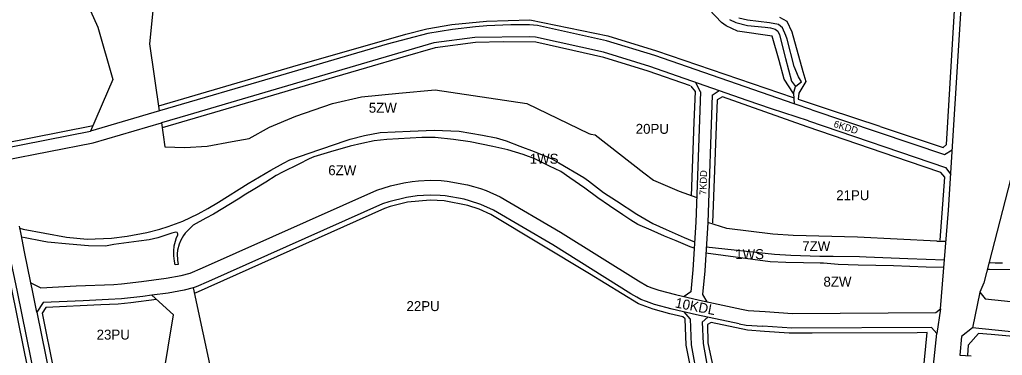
# Model space of a CAD drawing. Extents: x 7428203 to 7432868, y 5542672 to 5545406.
# Drawn here: x 7430430 to 7431420, y 5544524 to 5544863 of the extents above; entities that cross this region are included whole.
import ezdxf

# ---------------------------------------------------------------- set-up
doc = ezdxf.new("R2010")
doc.units = 0
for name, color, linetype in [('_GRANICA_MIASTA', 7, 'Continuous'), ('granicaBulwary', 7, 'Continuous'), ('MPZP_uchwalone_nieobowiazujace jeszcze_SZRAF', 7, 'Continuous')]:
    doc.layers.add(name, color=color, linetype=linetype)

msp = doc.modelspace()

# ---------------------------------------------------------------- linework, layer by layer
at = {"layer": '_GRANICA_MIASTA'}
for p, q in [((7430403.81, 5545093.47), (7430508.77, 5544854.93)), ((7431365.56, 5544670.63), (7431383.69, 5544964.48)), ((7430561.2, 5544838.24), (7430570.79, 5544936.38)), ((7431145.02, 5544862.64), (7431151.24, 5544859.72)), ((7431151.24, 5544859.72), (7431163.08, 5544856.79)), ((7430508.77, 5544854.93), (7430523.8, 5544802.28)), ((7430841.3, 5544848.45), (7430800.25, 5544837.84)), ((7430865.99, 5544852.6), (7430841.3, 5544848.45)), ((7430889.02, 5544855.39), (7430865.99, 5544852.6)), ((7430900.65, 5544856.15), (7430889.02, 5544855.39)), ((7430924.73, 5544857.4), (7430900.65, 5544856.15)), ((7430943.5, 5544857.43), (7430924.73, 5544857.4)), ((7430951.44, 5544856.57), (7430943.5, 5544857.43)), ((7431021.13, 5544841.34), (7430951.44, 5544856.57)), ((7431163.08, 5544856.79), (7431181.02, 5544854.93)), ((7431181.02, 5544854.93), (7431186.08, 5544854.4)), ((7431186.08, 5544854.4), (7431191.09, 5544853.08)), ((7431191.09, 5544853.08), (7431193.77, 5544851.02)), ((7431193.77, 5544851.02), (7431195.22, 5544847.14)), ((7430847.35, 5544839.01), (7430743.03, 5544808.53)), ((7430888.49, 5544844.44), (7430847.35, 5544839.01)), ((7430943.35, 5544845.35), (7430888.49, 5544844.44)), ((7430949.65, 5544844.83), (7430943.35, 5544845.35)), ((7431018.07, 5544829.73), (7430949.65, 5544844.83)), ((7431069.71, 5544826.5), (7431021.13, 5544841.34)), ((7431195.22, 5544847.14), (7431201.29, 5544823.27)), ((7430571.05, 5544770.59), (7430561.2, 5544838.24)), ((7430800.25, 5544837.84), (7430692.89, 5544806.33)), ((7431064.73, 5544815.47), (7431018.07, 5544829.73)), ((7431210.02, 5544777.67), (7431069.71, 5544826.5)), ((7431201.29, 5544823.27), (7431207.5, 5544800.46)), ((7431162.79, 5544781.23), (7431064.73, 5544815.47)), ((7430523.8, 5544802.28), (7430501.57, 5544750.21)), ((7430692.89, 5544806.33), (7430571.05, 5544770.59)), ((7430743.03, 5544808.53), (7430599.4, 5544766.41)), ((7431115.79, 5544789.85), (7431110.76, 5544799.4)), ((7431207.5, 5544800.46), (7431211.4, 5544795.35)), ((7430811.81, 5544788.58), (7430848.68, 5544791.74)), ((7430848.68, 5544791.74), (7430940.83, 5544778.13)), ((7431115.79, 5544789.85), (7431111, 5544658.59)), ((7431127.61, 5544786.5), (7431134.58, 5544791.08)), ((7430745.25, 5544778.21), (7430774.51, 5544784.82)), ((7430774.51, 5544784.82), (7430811.81, 5544788.58)), ((7431127.61, 5544786.5), (7431122.99, 5544658.15)), ((7431187.25, 5544772.69), (7431162.79, 5544781.23)), ((7431209.44, 5544788.08), (7431210.02, 5544777.67)), ((7430571.05, 5544770.59), (7430501.57, 5544750.21)), ((7430708.23, 5544765.47), (7430745.25, 5544778.21)), ((7430940.83, 5544778.13), (7431003.36, 5544748)), ((7431224.37, 5544760.47), (7431187.25, 5544772.69)), ((7431227.72, 5544771.68), (7431210.02, 5544777.67)), ((7431227.72, 5544771.68), (7431361.56, 5544726.7)), ((7430599.4, 5544766.41), (7430572.79, 5544758.6)), ((7430681.56, 5544754.21), (7430708.23, 5544765.47)), ((7430504.28, 5544738.51), (7430572.79, 5544758.6)), ((7430572.79, 5544758.6), (7430576.3, 5544734.53)), ((7430661.36, 5544742.68), (7430681.56, 5544754.21)), ((7430619.03, 5544735.1), (7430644.11, 5544739.65)), ((7430644.11, 5544739.65), (7430661.36, 5544742.68)), ((7431003.36, 5544748), (7431005.28, 5544747.05)), ((7431005.28, 5544747.05), (7431009.5, 5544746.41)), ((7431009.5, 5544746.41), (7431058.51, 5544708.25)), ((7430576.3, 5544734.53), (7430596.47, 5544733.89)), ((7430596.47, 5544733.89), (7430619.03, 5544735.1)), ((7431361.56, 5544726.7), (7431369.31, 5544731.46)), ((7430825.25, 5544699.49), (7430831.85, 5544700.17)), ((7430831.85, 5544700.17), (7430843.59, 5544700.67)), ((7430843.59, 5544700.67), (7430854.46, 5544700.34)), ((7430854.46, 5544700.34), (7430860.64, 5544699.81)), ((7431058.51, 5544708.25), (7431068.41, 5544701)), ((7431068.41, 5544701), (7431094.28, 5544689.83)), ((7430614.27, 5544612.53), (7430789.81, 5544690.81)), ((7430789.81, 5544690.81), (7430803.47, 5544695.18)), ((7430803.47, 5544695.18), (7430816.98, 5544698.24)), ((7430816.98, 5544698.24), (7430825.25, 5544699.49)), ((7430860.64, 5544699.81), (7430880.99, 5544696.26)), ((7430880.99, 5544696.26), (7430887.3, 5544694.58)), ((7430887.3, 5544694.58), (7430894.33, 5544692.36)), ((7430894.33, 5544692.36), (7430899.97, 5544690.31)), ((7430899.97, 5544690.31), (7430914.06, 5544684.05)), ((7430819.63, 5544683.47), (7430801.98, 5544679.1)), ((7430830.27, 5544684.96), (7430819.63, 5544683.47)), ((7430836.63, 5544685.46), (7430830.27, 5544684.96)), ((7430843.61, 5544685.67), (7430836.63, 5544685.46)), ((7430853.49, 5544685.37), (7430843.61, 5544685.67)), ((7430858.6, 5544684.94), (7430853.49, 5544685.37)), ((7430877.77, 5544681.6), (7430858.6, 5544684.94)), ((7430883.11, 5544680.17), (7430877.77, 5544681.6)), ((7430894.36, 5544676.39), (7430883.11, 5544680.17)), ((7430914.06, 5544684.05), (7430974.84, 5544648.56)), ((7431094.28, 5544689.83), (7431111.9, 5544683.37)), ((7430795.4, 5544676.88), (7430620.35, 5544598.82)), ((7430801.98, 5544679.1), (7430795.4, 5544676.88)), ((7430907.22, 5544670.68), (7430894.36, 5544676.39)), ((7430967.07, 5544635.73), (7430907.22, 5544670.68)), ((7431357.47, 5544571.25), (7431365.56, 5544670.63)), ((7430431.55, 5544646.37), (7430429.88, 5544654.63)), ((7430435.12, 5544628.69), (7430431.55, 5544646.37)), ((7430974.84, 5544648.56), (7431053.21, 5544599.28)), ((7431209.07, 5544645.23), (7431188.63, 5544646.48)), ((7431273.81, 5544643.32), (7431209.07, 5544645.23)), ((7431353.8, 5544639.43), (7431273.81, 5544643.32)), ((7431045.61, 5544586.34), (7430967.07, 5544635.73)), ((7431353.8, 5544639.43), (7431363.01, 5544639.34)), ((7430441.47, 5544597.29), (7430435.12, 5544628.69)), ((7430601.92, 5544607.08), (7430614.27, 5544612.53)), ((7430552.94, 5544598.65), (7430577.56, 5544601.96)), ((7430577.56, 5544601.96), (7430592.8, 5544604.73)), ((7430592.8, 5544604.73), (7430601.92, 5544607.08)), ((7430441.47, 5544597.29), (7430451.33, 5544592.35)), ((7430442.65, 5544591.45), (7430441.47, 5544597.29)), ((7430447.41, 5544567.9), (7430442.65, 5544591.45)), ((7430451.33, 5544592.35), (7430487, 5544594.33)), ((7430487, 5544594.33), (7430525.05, 5544595.88)), ((7430525.05, 5544595.88), (7430532.62, 5544596.25)), ((7430532.62, 5544596.25), (7430552.94, 5544598.65)), ((7430604.98, 5544592.38), (7430595.88, 5544590.06)), ((7430607.98, 5544593.36), (7430604.98, 5544592.38)), ((7430604.98, 5544592.38), (7430633.38, 5544460.3)), ((7430620.35, 5544598.82), (7430607.98, 5544593.36)), ((7431053.21, 5544599.28), (7431062.4, 5544594.22)), ((7431062.4, 5544594.22), (7431066.89, 5544592.35)), ((7431066.89, 5544592.35), (7431073.65, 5544589.97)), ((7430579.6, 5544587.13), (7430563.07, 5544584.92)), ((7430595.88, 5544590.06), (7430579.6, 5544587.13)), ((7431051.78, 5544582.96), (7431045.61, 5544586.34)), ((7431055.82, 5544580.76), (7431051.78, 5544582.96)), ((7431073.65, 5544589.97), (7431090.64, 5544585.6)), ((7431090.64, 5544585.6), (7431114.84, 5544579.86)), ((7431106.12, 5544588.35), (7431099.2, 5544583.57)), ((7431117.72, 5544585.56), (7431122.28, 5544578.31)), ((7431397.08, 5544588.16), (7431389.69, 5544552.15)), ((7431061.21, 5544578.44), (7431055.82, 5544580.76)), ((7431069.28, 5544575.6), (7431061.21, 5544578.44)), ((7431087.05, 5544571.04), (7431069.28, 5544575.6)), ((7431114.84, 5544579.86), (7431157.01, 5544571.05)), ((7431352.86, 5544567.36), (7431357.47, 5544571.25)), ((7431357.47, 5544571.25), (7431353.84, 5544546.3)), ((7431111.57, 5544565.22), (7431087.05, 5544571.04)), ((7431105.3, 5544561.03), (7431099.31, 5544568.13)), ((7431154.56, 5544556.24), (7431111.57, 5544565.22)), ((7431117.44, 5544557.87), (7431123.24, 5544562.78)), ((7431180.91, 5544568.49), (7431208.29, 5544566.66)), ((7431208.29, 5544566.66), (7431352.86, 5544567.36)), ((7431154.56, 5544556.24), (7431161.78, 5544554.73)), ((7431161.78, 5544554.73), (7431178.45, 5544553.62)), ((7431207.83, 5544551.66), (7431178.45, 5544553.62)), ((7431348.46, 5544552.28), (7431207.83, 5544551.66)), ((7431353.84, 5544546.3), (7431348.46, 5544552.28)), ((7431389.69, 5544552.15), (7431378.65, 5544543.23)), ((7431346.8, 5544481.9), (7431353.84, 5544546.3)), ((7431378.65, 5544543.23), (7431376.85, 5544524.65)), ((7431376.85, 5544524.65), (7431388.4, 5544523.8))]:
    msp.add_line(p, q, dxfattribs=at)
for points in [[(7431217.55, 5544800.01), (7431214.53, 5544804.81), (7431210.03, 5544815.18), (7431202.94, 5544842.84), (7431201.83, 5544846.62), (7431198.25, 5544854.3), (7431194.18, 5544857.5), (7431185.19, 5544859.44), (7431163.15, 5544862.15), (7431154.24, 5544864.1)], [(7431209.44, 5544788.08), (7431211.4, 5544795.35), (7431215.13, 5544798.31), (7431217.55, 5544800.01)], [(7431443.89, 5544793.65), (7431441.13, 5544760.73), (7431430.72, 5544711.87), (7431401.06, 5544597.34), (7431397.08, 5544588.16), (7431402.52, 5544581.13), (7431564.3, 5544564.44), (7431796.47, 5544548.52), (7432036.81, 5544532.49), (7432066.29, 5544550.26), (7432068.15, 5544576.37), (7432070.42, 5544592.86), (7432074.81, 5544612.13), (7432081.47, 5544701.72)], [(7431224.37, 5544760.47), (7431362.34, 5544713.5), (7431367.77, 5544706.56)], [(7430401.61, 5544731.97), (7430411.28, 5544732.5), (7430501.57, 5544750.21)], [(7430430.33, 5544652.41), (7430433.75, 5544651.57), (7430477.33, 5544643.39), (7430498.23, 5544641.55), (7430522.65, 5544642.44), (7430538.37, 5544644.48), (7430558.31, 5544647.97), (7430571.2, 5544651.38), (7430579.78, 5544654.31), (7430594.58, 5544659.49), (7430609.79, 5544666.87), (7430619.61, 5544672.44), (7430630.29, 5544678.54), (7430660.2, 5544697.48), (7430683.11, 5544711.05), (7430695.65, 5544718), (7430702.27, 5544721.35), (7430732.53, 5544731.63), (7430749.29, 5544737.39), (7430756.05, 5544739.95), (7430762.81, 5544742.21), (7430777.37, 5544745.99), (7430793.07, 5544748.71), (7430823.24, 5544750.14), (7430847.65, 5544751.23), (7430872.75, 5544750.06), (7430896.16, 5544746.23), (7430909.95, 5544743.43), (7430919.92, 5544740.35), (7430933.75, 5544735.14), (7430948.08, 5544729.86), (7430965.98, 5544722.43), (7430973.21, 5544718.15), (7430998.25, 5544703.65), (7431002.82, 5544700.14), (7431018.21, 5544688.33), (7431031.08, 5544680), (7431051.6, 5544666.51), (7431067.68, 5544657.31), (7431081.1, 5544651.25), (7431099.23, 5544643.04), (7431109.78, 5544638.75)], [(7431109.38, 5544632.29), (7431105.27, 5544633.78), (7431091.12, 5544639.57), (7431079.5, 5544644.28), (7431066.13, 5544650.4), (7431052.57, 5544656.11), (7431045.74, 5544660.41), (7431037.36, 5544665.94), (7431024.17, 5544674.95), (7431012.41, 5544683.13), (7430999.19, 5544692.84), (7430984.05, 5544703.27), (7430975.25, 5544709.57), (7430963.74, 5544714.99), (7430948.84, 5544722.24), (7430937.03, 5544726.63), (7430921.72, 5544731.48), (7430906.57, 5544734.85), (7430883.87, 5544739.3), (7430866.97, 5544741.79), (7430848.5, 5544743.83), (7430834.98, 5544743.78), (7430799.96, 5544741.76), (7430787.19, 5544740.45), (7430774.58, 5544737.65), (7430763.06, 5544734.99), (7430743.21, 5544729.21), (7430726.41, 5544724.25), (7430721.81, 5544722.47), (7430711.14, 5544717.09), (7430694.77, 5544708.96), (7430688.45, 5544705.42), (7430677.88, 5544698.93), (7430665.17, 5544691.25), (7430657.71, 5544686.57), (7430650.05, 5544681.68), (7430625.32, 5544666.43), (7430617.63, 5544662.44), (7430604.98, 5544655.54), (7430601.55, 5544652.02), (7430596.86, 5544647.55), (7430595.07, 5544644.99), (7430592.57, 5544640.52), (7430590.85, 5544636.47), (7430588.9, 5544630.42), (7430588.76, 5544626.63), (7430589.01, 5544620.38), (7430589.69, 5544615.93), (7430586.73, 5544615.41), (7430586.18, 5544619.07), (7430585.47, 5544624.51), (7430585.47, 5544629.19), (7430585.85, 5544634.56), (7430586.95, 5544639.28), (7430588, 5544642.91), (7430589.48, 5544645.55), (7430589.53, 5544646.85), (7430588.69, 5544648.01), (7430587.28, 5544648.35), (7430583.34, 5544647.39), (7430569.32, 5544642.74), (7430560.55, 5544640.7), (7430550.02, 5544639.38), (7430524.81, 5544635.87), (7430516.71, 5544634.44), (7430499.41, 5544634.64), (7430479.8, 5544636.43), (7430458.15, 5544638.43), (7430452.74, 5544639.41), (7430435.5, 5544642.88), (7430432.12, 5544643.55)], [(7430408.1, 5544720.43), (7430414.93, 5544720.99), (7430504.28, 5544738.51)], [(7431111, 5544658.59), (7431108.04, 5544610.44), (7431106.12, 5544588.35)], [(7431122.99, 5544658.15), (7431120.01, 5544609.5), (7431117.72, 5544585.56)], [(7431188.63, 5544646.48), (7431142.19, 5544652.26), (7431122.99, 5544658.15)], [(7431361.45, 5544620.11), (7431324.43, 5544621.74), (7431282.41, 5544623.32), (7431275.83, 5544623.65), (7431249.28, 5544623.86), (7431236.01, 5544623.92), (7431206.63, 5544625.11), (7431190.39, 5544625.95), (7431121.46, 5544633.23)], [(7430457.97, 5544439.94), (7430446.05, 5544498.9), (7430427.95, 5544588.48), (7430420.35, 5544625.11)], [(7431121.12, 5544627.71), (7431185.81, 5544618.8), (7431201.65, 5544618.15), (7431219.35, 5544617.87), (7431236.27, 5544617.46), (7431239.75, 5544617.41), (7431254.31, 5544616.21), (7431274.68, 5544615.44), (7431310, 5544614.79), (7431343.05, 5544613.64), (7431360.89, 5544613.26)], [(7431404.66, 5544611.23), (7431406.67, 5544611.13), (7431427.51, 5544610.68)], [(7431419.97, 5544617.18), (7431412.41, 5544617.3), (7431407.57, 5544617.4), (7431406.29, 5544617.52)], [(7430470.09, 5544455.7), (7430465.74, 5544477.21), (7430472.67, 5544471.8), (7430489.65, 5544474.52), (7430521.79, 5544476.48), (7430553.88, 5544471.74), (7430569.42, 5544469.51), (7430584.87, 5544565.16), (7430563.07, 5544584.92), (7430554.24, 5544583.75), (7430532.74, 5544581.22), (7430519.71, 5544580.53), (7430493.95, 5544579.21), (7430453.82, 5544577.48), (7430447.41, 5544567.9), (7430460.75, 5544501.87), (7430465.74, 5544477.21)], [(7431157.01, 5544571.05), (7431163.82, 5544569.63), (7431180.91, 5544568.49)], [(7431105.3, 5544561.03), (7431106.35, 5544535.11), (7431112.57, 5544499.95), (7431120.29, 5544466.13), (7431123.22, 5544441.19), (7431126.91, 5544409.92), (7431128.31, 5544398.07), (7431129.4, 5544389.65), (7431128.94, 5544382.08), (7431127.83, 5544377.61)], [(7431117.44, 5544557.87), (7431118.31, 5544536.4), (7431124.33, 5544502.33), (7431132.13, 5544468.17), (7431140.22, 5544399.55), (7431141.45, 5544390.06), (7431140.85, 5544380.26), (7431139.48, 5544374.73)], [(7431654.46, 5543877.07), (7431672.85, 5544147.41), (7431697.38, 5544505.35), (7431680.1, 5544526.46), (7431451.66, 5544545.79), (7431389.69, 5544552.15)]]:
    msp.add_lwpolyline(points, dxfattribs=at)
at = {"layer": 'MPZP_uchwalone_nieobowiazujace jeszcze_SZRAF'}
for p, q in [((7431205.18, 5544546.83), (7431180.04, 5544548.5)), ((7431228.25, 5544546.75), (7431205.18, 5544546.83)), ((7431333.82, 5544547.21), (7431228.25, 5544546.75))]:
    msp.add_line(p, q, dxfattribs=at)
for points in [[(7431296.77, 5544754.97), (7431359.99, 5544733.86), (7431363.63, 5544736.87), (7431373.38, 5544905.67), (7431383.45, 5545079.98)], [(7431209.44, 5544788.08), (7431199.87, 5544802.6), (7431194.93, 5544821.53), (7431187.78, 5544846.05), (7431152.97, 5544850.96), (7431141.5, 5544856.16), (7431136.76, 5544859.65), (7431105.84, 5544892.49)], [(7430570.37, 5544775.6), (7430705.07, 5544815.42), (7430818.97, 5544847.82), (7430840.26, 5544853.35), (7430865.27, 5544857.55), (7430900.35, 5544861.14), (7430943.82, 5544862.42), (7431022.4, 5544846.19), (7431071.35, 5544831.22), (7431208.91, 5544784.13)], [(7431195.37, 5544865.03), (7431202.67, 5544860.95), (7431207.84, 5544850.32), (7431218.72, 5544810.24), (7431221.93, 5544800.12), (7431214.63, 5544788.56), (7431214.08, 5544782.39), (7431244.22, 5544772.34), (7431296.48, 5544755.11)], [(7431105.68, 5544795.88), (7431063.18, 5544810.72), (7431018.54, 5544824.36), (7430987.03, 5544831.46), (7430949.94, 5544839.78), (7430917.13, 5544840.06), (7430889.15, 5544839.48), (7430848.38, 5544834.1), (7430816.02, 5544824.65), (7430779.31, 5544813.92), (7430747.17, 5544804.53), (7430670.86, 5544781.93), (7430573.52, 5544753.61)], [(7431106.79, 5544685.15), (7431109.43, 5544759.38), (7431110.79, 5544790.03), (7431106.29, 5544795.67)], [(7431357.09, 5544640.5), (7431361.73, 5544703.74), (7431357.87, 5544708.48), (7431325.14, 5544719.67), (7431223.18, 5544754.43), (7431137.75, 5544784.76), (7431132.38, 5544781.63), (7431127.98, 5544657.97)], [(7430403.26, 5544737.07), (7430410.66, 5544737.47), (7430504.22, 5544755.83)], [(7431097.8, 5544563.11), (7431085.02, 5544566.28), (7431068.04, 5544570.76), (7431053.43, 5544576.37), (7431004.01, 5544606.59), (7430904.7, 5544666.36), (7430892.77, 5544671.65), (7430881.52, 5544675.43), (7430857.73, 5544679.93), (7430843.46, 5544680.67), (7430820.83, 5544678.62), (7430803.18, 5544674.25), (7430797.44, 5544672.31), (7430606.82, 5544587.15)], [(7430452.96, 5544439.48), (7430449.8, 5544455.13), (7430442.03, 5544493.58), (7430434.78, 5544529.46), (7430415.09, 5544626.01)], [(7430567.92, 5544580.53), (7430542.08, 5544577.28), (7430529.17, 5544576.02), (7430511.85, 5544575.12), (7430456.57, 5544572.6), (7430452.66, 5544566.75), (7430464.55, 5544508.32), (7430470.27, 5544480.01), (7430474.03, 5544477.08), (7430489.96, 5544479.56), (7430519.47, 5544481.48), (7430530.94, 5544480.24), (7430560.29, 5544475.87), (7430570.21, 5544474.44)], [(7431063.14, 5544382.37), (7431110.81, 5544354.59), (7431113.93, 5544356.36), (7431123.48, 5544380.83), (7431124.35, 5544388.98), (7431114.91, 5544466.23), (7431101.37, 5544534.57), (7431100.3, 5544560.99), (7431097.8, 5544563.11)], [(7431180.04, 5544548.5), (7431162.91, 5544549.87), (7431126.42, 5544557.33), (7431122.79, 5544555.58), (7431123.29, 5544536.94), (7431137.91, 5544467.8), (7431146.47, 5544390.23), (7431146.14, 5544384.86), (7431145.52, 5544378.33), (7431144.09, 5544372.8), (7431133.54, 5544345.78)], [(7431301.89, 5544212.52), (7431311.45, 5544211.59), (7431313.56, 5544233.49), (7431323.58, 5544337.28), (7431343.89, 5544547.26), (7431333.82, 5544547.21)], [(7431408.5, 5544545.23), (7431395.74, 5544546.5), (7431385.32, 5544534.64), (7431384.5, 5544524.49)], [(7431649.47, 5543877.41), (7431655.88, 5543974.89), (7431665.17, 5544116.21), (7431681.81, 5544351.27), (7431692.14, 5544503.86), (7431677.57, 5544521.65), (7431530.62, 5544534.23), (7431408.5, 5544545.23)]]:
    msp.add_lwpolyline(points, dxfattribs=at)

# ---------------------------------------------------------------- texts
at = {"layer": 'granicaBulwary'}
for s, p in [('5ZW', (7430781.73, 5544768.77)), ('20PU', (7431050.5, 5544747.53)), ('1WS', (7430943.76, 5544717.41)), ('6ZW', (7430740.9, 5544705.82)), ('21PU', (7431252.39, 5544680.65)), ('1WS', (7431150.7, 5544621.32)), ('7ZW', (7431218.18, 5544629.34)), ('8ZW', (7431239.55, 5544593.58)), ('22PU', (7430819.66, 5544568.97)), ('23PU', (7430507.62, 5544540.25))]:
    msp.add_text(s, height=10, dxfattribs=at).set_placement(p)
for s, height, rotation, p in [('6KDD', 7, 342.42545, (7431249.25, 5544754.59)), ('7KDD', 7, 88.37265, (7431121.66, 5544685.8)), ('10KDL', 10, 348.88506, (7431089.63, 5544572.73))]:
    msp.add_text(s, height=height, rotation=rotation, dxfattribs=at).set_placement(p)

doc.saveas('drawing.dxf')
